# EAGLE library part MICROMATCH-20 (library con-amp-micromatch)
MicroMaTch 20 9-215464-0 / 2-215464-0 Drawing Number C-215464 DDEController.pdf
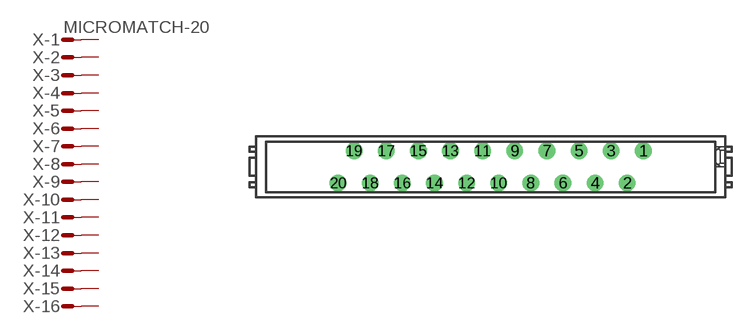
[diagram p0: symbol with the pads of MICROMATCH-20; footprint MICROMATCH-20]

Designator prefix X; gates -1=MV -2=M -3=M -4=M -5=M -6=M -7=M -8=M -9=M -10=M -11=M -12=M -13=M -14=M -15=M -16=M -17=M -18=M -19=M -20=M

## MICROMATCH-20 (MF: FARNELL; MPN: 9-215464-0; OC_FARNELL: 3784708; OC_NEWARK: 19J6798)  [MICROMATCH-20]
1  -1:S  pas
2  -2:S  pas
3  -3:S  pas
4  -4:S  pas
5  -5:S  pas
6  -6:S  pas
7  -7:S  pas
8  -8:S  pas
9  -9:S  pas
10  -10:S  pas
11  -11:S  pas
12  -12:S  pas
13  -13:S  pas
14  -14:S  pas
15  -15:S  pas
16  -16:S  pas
17  -17:S  pas
18  -18:S  pas
19  -19:S  pas
20  -20:S  pas

## Footprint MICROMATCH-20 (pad centres in mm)
MicroMaTch 20 9-215464-0 / 2-215464-0 Drawing Number C-215464 DDEController.pdf
drill 0.813 round: 1 12.065,1.27; 2 10.795,-1.27; 3 9.525,1.27; 4 8.255,-1.27; 5 6.985,1.27; 6 5.715,-1.27; 7 4.445,1.27; 8 3.175,-1.27; 9 1.905,1.27; 10 0.635,-1.27; 11 -0.635,1.27; 12 -1.905,-1.27; 13 -3.175,1.27; 14 -4.445,-1.27; 15 -5.715,1.27; 16 -6.985,-1.27; 17 -8.255,1.27; 18 -9.525,-1.27; 19 -10.795,1.27; 20 -12.065,-1.27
